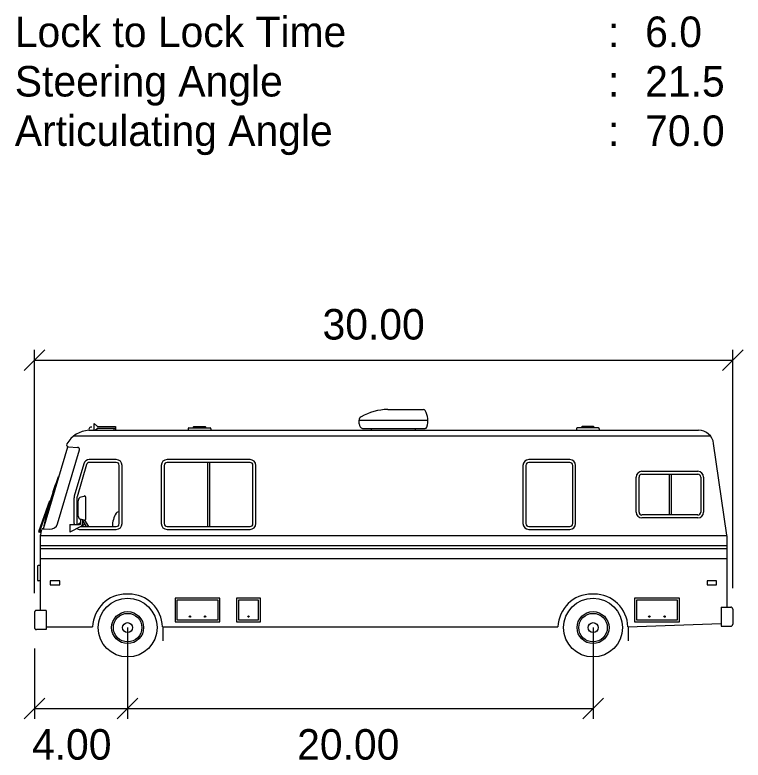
# Model space of a CAD drawing. Extents: x 2297881 to 2300600, y 559917 to 564426.
# Drawn here: x 2299111.91 to 2299143.2, y 562688.72 to 562720.74 of the extents above; entities that cross this region are included whole.
import ezdxf

# ---------------------------------------------------------------- set-up
doc = ezdxf.new("R2010")
doc.units = 0
doc.layers.add('DR_X_Elev_Flow', color=7, linetype='Continuous')

msp = doc.modelspace()

# ---------------------------------------------------------------- linework, layer by layer
at = {"layer": 'DR_X_Elev_Flow'}
for p, q in [((2299113.197, 562706.353), (2299112.311, 562705.467)), ((2299112.754, 562695.893), (2299112.754, 562706.353)), ((2299143.197, 562706.353), (2299142.311, 562705.467)), ((2299142.754, 562696.118), (2299142.754, 562706.353)), ((2299112.754, 562705.91), (2299142.754, 562705.91)), ((2299127.931, 562703.792), (2299129.471, 562703.792)), ((2299126.699, 562703.335), (2299129.652, 562703.335)), ((2299126.699, 562703.168), (2299126.699, 562703.335)), ((2299115.312, 562702.895), (2299115.312, 562703.187)), ((2299115.312, 562703.187), (2299115.459, 562703.062)), ((2299115.359, 562702.895), (2299115.459, 562702.981)), ((2299115.459, 562703.062), (2299116.237, 562703.062)), ((2299115.459, 562702.981), (2299116.237, 562702.981)), ((2299116.164, 562702.981), (2299116.164, 562702.895)), ((2299116.237, 562703.062), (2299116.237, 562702.895)), ((2299119.384, 562702.995), (2299120.302, 562702.995)), ((2299119.605, 562703.056), (2299120.081, 562703.056)), ((2299126.845, 562702.978), (2299129.531, 562702.978)), ((2299127.217, 562702.978), (2299127.217, 562702.895)), ((2299129.11, 562702.978), (2299129.11, 562702.895)), ((2299136.987, 562702.995), (2299136.068, 562702.995)), ((2299136.766, 562703.056), (2299136.29, 562703.056)), ((2299115.088, 562702.895), (2299141.283, 562702.895)), ((2299119.351, 562702.962), (2299119.351, 562702.895)), ((2299120.335, 562702.962), (2299120.335, 562702.895)), ((2299136.036, 562702.962), (2299136.036, 562702.895)), ((2299137.02, 562702.962), (2299137.02, 562702.895)), ((2299141.797, 562702.647), (2299114.429, 562702.647)), ((2299113.144, 562698.664), (2299114.181, 562702.19)), ((2299113.743, 562698.883), (2299114.682, 562702.055)), ((2299114.212, 562702.188), (2299114.609, 562702.16)), ((2299142.503, 562698.383), (2299141.932, 562702.333)), ((2299114.87, 562701.459), (2299114.462, 562700.071)), ((2299114.989, 562701.423), (2299114.581, 562700.035)), ((2299116.269, 562701.638), (2299115.109, 562701.638)), ((2299116.269, 562701.513), (2299115.109, 562701.513)), ((2299116.394, 562698.885), (2299116.394, 562701.388)), ((2299116.519, 562698.885), (2299116.519, 562701.388)), ((2299118.201, 562701.388), (2299118.201, 562698.885)), ((2299118.326, 562701.388), (2299118.326, 562698.885)), ((2299122.016, 562701.638), (2299118.451, 562701.638)), ((2299122.016, 562701.513), (2299118.451, 562701.513)), ((2299120.192, 562701.513), (2299120.192, 562698.76)), ((2299120.274, 562701.513), (2299120.274, 562698.76)), ((2299122.141, 562698.885), (2299122.141, 562701.388)), ((2299122.265, 562698.885), (2299122.265, 562701.388)), ((2299133.74, 562701.388), (2299133.74, 562698.885)), ((2299133.864, 562701.388), (2299133.864, 562698.885)), ((2299135.75, 562701.638), (2299133.989, 562701.638)), ((2299135.75, 562701.513), (2299133.989, 562701.513)), ((2299135.875, 562698.885), (2299135.875, 562701.388)), ((2299135.999, 562698.885), (2299135.999, 562701.388)), ((2299138.852, 562701.133), (2299141.251, 562701.133)), ((2299113.771, 562700.902), (2299113.8, 562700.894)), ((2299138.602, 562699.381), (2299138.602, 562700.884)), ((2299138.727, 562699.381), (2299138.727, 562700.884)), ((2299138.852, 562701.009), (2299141.251, 562701.009)), ((2299140.019, 562701.009), (2299140.019, 562699.257)), ((2299140.101, 562701.009), (2299140.101, 562699.257)), ((2299141.376, 562700.884), (2299141.376, 562699.381)), ((2299141.501, 562700.884), (2299141.501, 562699.381)), ((2299113.405, 562699.862), (2299112.925, 562698.53)), ((2299112.973, 562698.516), (2299113.428, 562699.857)), ((2299113.405, 562699.862), (2299113.428, 562699.857)), ((2299114.451, 562700), (2299114.451, 562698.885)), ((2299114.576, 562700), (2299114.576, 562698.885)), ((2299114.633, 562699.199), (2299114.633, 562699.872)), ((2299114.75, 562700.03), (2299114.89, 562700.071)), ((2299114.944, 562700.035), (2299114.944, 562699.066)), ((2299141.251, 562699.257), (2299138.852, 562699.257)), ((2299141.251, 562699.132), (2299138.852, 562699.132)), ((2299114.271, 562698.843), (2299114.271, 562698.525)), ((2299114.271, 562698.843), (2299114.687, 562698.843)), ((2299114.592, 562698.843), (2299114.746, 562698.936)), ((2299114.891, 562699.029), (2299114.722, 562699.079)), ((2299114.746, 562698.902), (2299114.746, 562699.069)), ((2299114.783, 562698.788), (2299114.925, 562698.873)), ((2299114.812, 562699.044), (2299114.812, 562698.868)), ((2299114.812, 562698.975), (2299114.85, 562698.998)), ((2299114.992, 562698.76), (2299114.818, 562699.051)), ((2299115.083, 562698.758), (2299114.921, 562699.03)), ((2299112.925, 562698.53), (2299113.027, 562698.5)), ((2299112.996, 562698.595), (2299113.05, 562698.579)), ((2299113.02, 562698.475), (2299113.068, 562698.638)), ((2299113.108, 562698.666), (2299113.41, 562698.649)), ((2299113.151, 562698.792), (2299113.18, 562698.784)), ((2299114.742, 562698.756), (2299114.271, 562698.525)), ((2299114.701, 562698.636), (2299116.269, 562698.636)), ((2299114.75, 562698.76), (2299116.269, 562698.76)), ((2299118.451, 562698.76), (2299122.016, 562698.76)), ((2299118.451, 562698.636), (2299122.016, 562698.636)), ((2299133.989, 562698.76), (2299135.75, 562698.76)), ((2299133.989, 562698.636), (2299135.75, 562698.636)), ((2299113.003, 562698.372), (2299142.504, 562698.372)), ((2299113.003, 562698.372), (2299113.003, 562695.155)), ((2299142.504, 562698.36), (2299142.504, 562695.298)), ((2299113.003, 562697.945), (2299142.504, 562697.945)), ((2299113.003, 562697.814), (2299142.504, 562697.814)), ((2299113.003, 562697.387), (2299142.504, 562697.387)), ((2299112.878, 562697.057), (2299112.878, 562696.459)), ((2299113.003, 562697.083), (2299112.905, 562697.083)), ((2299113.003, 562696.432), (2299112.905, 562696.432)), ((2299113.836, 562696.432), (2299113.426, 562696.432)), ((2299113.426, 562696.432), (2299113.426, 562696.25)), ((2299113.426, 562696.25), (2299113.836, 562696.25)), ((2299113.836, 562696.25), (2299113.836, 562696.432)), ((2299141.648, 562696.432), (2299141.648, 562696.25)), ((2299142.058, 562696.432), (2299141.648, 562696.432)), ((2299141.648, 562696.25), (2299142.058, 562696.25)), ((2299142.058, 562696.25), (2299142.058, 562696.432)), ((2299116.799, 562695.86), (2299116.705, 562695.86)), ((2299118.794, 562695.679), (2299118.794, 562694.666)), ((2299120.72, 562695.679), (2299118.794, 562695.679)), ((2299120.72, 562694.666), (2299120.72, 562695.679)), ((2299122.464, 562695.679), (2299121.433, 562695.679)), ((2299121.433, 562695.679), (2299121.433, 562694.666)), ((2299122.464, 562694.666), (2299122.464, 562695.679)), ((2299136.793, 562695.86), (2299136.698, 562695.86)), ((2299140.46, 562695.679), (2299138.534, 562695.679)), ((2299138.534, 562695.679), (2299138.534, 562694.666)), ((2299140.46, 562694.666), (2299140.46, 562695.679)), ((2299118.876, 562695.597), (2299118.876, 562694.748)), ((2299120.638, 562695.597), (2299118.876, 562695.597)), ((2299120.638, 562694.748), (2299120.638, 562695.597)), ((2299122.382, 562695.597), (2299121.515, 562695.597)), ((2299121.515, 562695.597), (2299121.515, 562694.748)), ((2299122.382, 562694.748), (2299122.382, 562695.597)), ((2299140.378, 562695.597), (2299138.616, 562695.597)), ((2299138.616, 562695.597), (2299138.616, 562694.748)), ((2299140.378, 562694.748), (2299140.378, 562695.597)), ((2299142.255, 562695.298), (2299142.672, 562695.298)), ((2299142.255, 562695.298), (2299142.255, 562694.477)), ((2299112.754, 562695.073), (2299112.754, 562694.417)), ((2299113.252, 562695.155), (2299112.836, 562695.155)), ((2299113.252, 562695.155), (2299113.252, 562694.335)), ((2299142.754, 562695.216), (2299142.754, 562694.559)), ((2299118.794, 562694.666), (2299120.72, 562694.666)), ((2299118.876, 562694.748), (2299120.638, 562694.748)), ((2299121.433, 562694.666), (2299122.464, 562694.666)), ((2299121.515, 562694.748), (2299122.382, 562694.748)), ((2299138.534, 562694.666), (2299140.46, 562694.666)), ((2299138.616, 562694.748), (2299140.378, 562694.748)), ((2299113.252, 562694.335), (2299112.836, 562694.335)), ((2299113.252, 562694.45), (2299115.25, 562694.45)), ((2299116.753, 562694.417), (2299116.753, 562690.498)), ((2299118.254, 562694.45), (2299135.244, 562694.45)), ((2299118.269, 562694.45), (2299118.269, 562693.843)), ((2299136.756, 562694.417), (2299136.756, 562690.498)), ((2299138.247, 562694.45), (2299142.255, 562694.589)), ((2299138.263, 562694.45), (2299138.263, 562693.843)), ((2299142.255, 562694.477), (2299142.672, 562694.477)), ((2299112.753, 562693.515), (2299112.753, 562690.498)), ((2299113.196, 562691.384), (2299112.31, 562690.498)), ((2299117.196, 562691.384), (2299116.31, 562690.498)), ((2299137.199, 562691.384), (2299136.313, 562690.498)), ((2299112.753, 562690.941), (2299136.756, 562690.941))]:
    msp.add_line(p, q, dxfattribs=at)
for centre, radius in [((2299116.756, 562694.417), 1.262), ((2299136.75, 562694.417), 1.262), ((2299116.756, 562694.417), 0.687), ((2299116.756, 562694.417), 0.613), ((2299136.75, 562694.417), 0.687), ((2299136.75, 562694.417), 0.613), ((2299119.429, 562694.889), 0.0292), ((2299120.085, 562694.889), 0.0292), ((2299121.948, 562694.889), 0.0292), ((2299139.169, 562694.889), 0.0292), ((2299139.825, 562694.889), 0.0292), ((2299116.753, 562694.417), 0.214), ((2299136.756, 562694.417), 0.214)]:
    msp.add_circle(centre, radius, dxfattribs=at)
for centre, radius, start, end in [((2299127.984, 562701.341), 2.451, 91.2494, 119.3414), ((2299129.471, 562703.71), 0.082, 28.1222, 90), ((2299128.731, 562703.314), 0.921, 342.3659, 28.1222), ((2299126.863, 562703.335), 0.164, 119.3414, 180), ((2299115.181, 562702.943), 0.0921, 68.355, 211.0903), ((2299119.384, 562702.962), 0.0328, 90, 180), ((2299119.62, 562702.993), 0.0647, 103.353, 178.0683), ((2299120.066, 562702.993), 0.0647, 1.9317, 76.647), ((2299120.302, 562702.962), 0.0328, 0, 90), ((2299126.899, 562703.17), 0.199, 180.5371, 254.2624), ((2299129.531, 562703.06), 0.082, 270, 342.3659), ((2299136.068, 562702.962), 0.0328, 90, 180), ((2299136.305, 562702.993), 0.0647, 103.353, 178.0683), ((2299136.751, 562702.993), 0.0647, 1.9317, 76.647), ((2299136.987, 562702.962), 0.0328, 0, 90), ((2299115.139, 562701.763), 1.133, 92.5824, 151.1904), ((2299141.283, 562702.239), 0.656, 8.2273, 90), ((2299114.218, 562702.27), 0.082, 151.1904, 266.0126), ((2299114.603, 562702.079), 0.082, 343.5195, 86.0126), ((2299115.109, 562701.388), 0.249, 90, 163.6201), ((2299115.109, 562701.388), 0.125, 90, 163.6201), ((2299116.269, 562701.388), 0.249, 360, 90), ((2299116.269, 562701.388), 0.125, 360, 90), ((2299118.451, 562701.388), 0.249, 90, 180), ((2299118.451, 562701.388), 0.125, 90, 180), ((2299122.016, 562701.388), 0.249, 360, 90), ((2299122.016, 562701.388), 0.125, 360, 90), ((2299133.989, 562701.388), 0.249, 90, 180), ((2299133.989, 562701.388), 0.125, 90, 180), ((2299135.75, 562701.388), 0.249, 360, 90), ((2299135.75, 562701.388), 0.125, 360, 90), ((2299138.852, 562700.884), 0.249, 90, 180), ((2299141.251, 562700.884), 0.249, 360, 90), ((2299130.403, 562694.867), 17.693, 160.0565, 167.1818), ((2299138.852, 562700.884), 0.125, 90, 180), ((2299141.251, 562700.884), 0.125, 360, 90), ((2299114.701, 562700), 0.249, 163.6202, 179.9999), ((2299114.701, 562700), 0.125, 163.6202, 179.9999), ((2299114.797, 562699.872), 0.164, 106.6018, 180), ((2299114.905, 562700.035), 0.0394, 0, 112.996), ((2299114.758, 562699.199), 0.125, 180, 253.4789), ((2299117.161, 562698.771), 1.06, 148.0256, 179.5058), ((2299116.386, 562699.235), 0.157, 87.0284, 141.8327), ((2299138.852, 562699.381), 0.249, 180, 270), ((2299138.852, 562699.381), 0.125, 180, 270), ((2299141.251, 562699.381), 0.249, 270, 0), ((2299141.251, 562699.381), 0.125, 270, 0), ((2299113.429, 562698.976), 0.328, 266.7124, 343.5195), ((2299114.701, 562698.885), 0.249, 180, 189.5855), ((2299114.701, 562698.885), 0.125, 180, 199.4534), ((2299114.687, 562698.902), 0.0591, 270, 0), ((2299114.688, 562698.868), 0.125, 296.1549, 360), ((2299114.905, 562699.066), 0.0394, 249.1388, 0), ((2299116.269, 562698.885), 0.125, 270, 0), ((2299116.269, 562698.885), 0.249, 270, 0), ((2299118.451, 562698.885), 0.249, 180, 270), ((2299118.451, 562698.885), 0.125, 180, 270), ((2299122.016, 562698.885), 0.249, 270, 0), ((2299122.016, 562698.885), 0.125, 270, 0), ((2299133.989, 562698.885), 0.249, 180, 270), ((2299133.989, 562698.885), 0.125, 180, 270), ((2299135.75, 562698.885), 0.125, 270, 0), ((2299135.75, 562698.885), 0.249, 270, 0), ((2299113.105, 562698.627), 0.0394, 86.7124, 163.6202), ((2299114.701, 562698.885), 0.249, 238.6328, 270), ((2299113.331, 562698.372), 0.328, 161.6774, 180), ((2299142.176, 562698.36), 0.328, 0, 3.965), ((2299112.905, 562697.057), 0.0262, 90, 180), ((2299112.905, 562696.459), 0.0262, 180, 270), ((2299116.705, 562694.404), 1.455, 90, 178.2022), ((2299116.799, 562694.404), 1.455, 1.7978, 90), ((2299136.698, 562694.404), 1.455, 90, 178.2022), ((2299136.793, 562694.404), 1.455, 1.7978, 90), ((2299142.672, 562695.216), 0.082, 0, 90), ((2299112.836, 562695.073), 0.082, 90, 180), ((2299112.836, 562694.417), 0.082, 180, 270), ((2299142.672, 562694.559), 0.082, 270, 0)]:
    msp.add_arc(centre, radius, start, end, dxfattribs=at)

# ---------------------------------------------------------------- texts
for s, height, p in [('Lock to Lock Time', 1.31234, (2299111.909, 562719.363)), ('6.0', 1.3123, (2299138.989, 562719.363)), (':', 1.312, (2299137.394, 562719.363)), ('Steering Angle', 1.31234, (2299111.909, 562717.238)), ('21.5', 1.3123, (2299138.989, 562717.238)), (':', 1.312, (2299137.394, 562717.238)), ('Articulating Angle', 1.31234, (2299111.909, 562715.113)), ('70.0', 1.3123, (2299138.989, 562715.113)), (':', 1.312, (2299137.394, 562715.113)), ('30.00', 1.3123, (2299125.129, 562706.796)), ('4.00', 1.3123, (2299112.647, 562688.743)), ('20.00', 1.3123, (2299124.038, 562688.743))]:
    msp.add_text(s, height=height, dxfattribs=at).set_placement(p)

doc.saveas('drawing.dxf')
